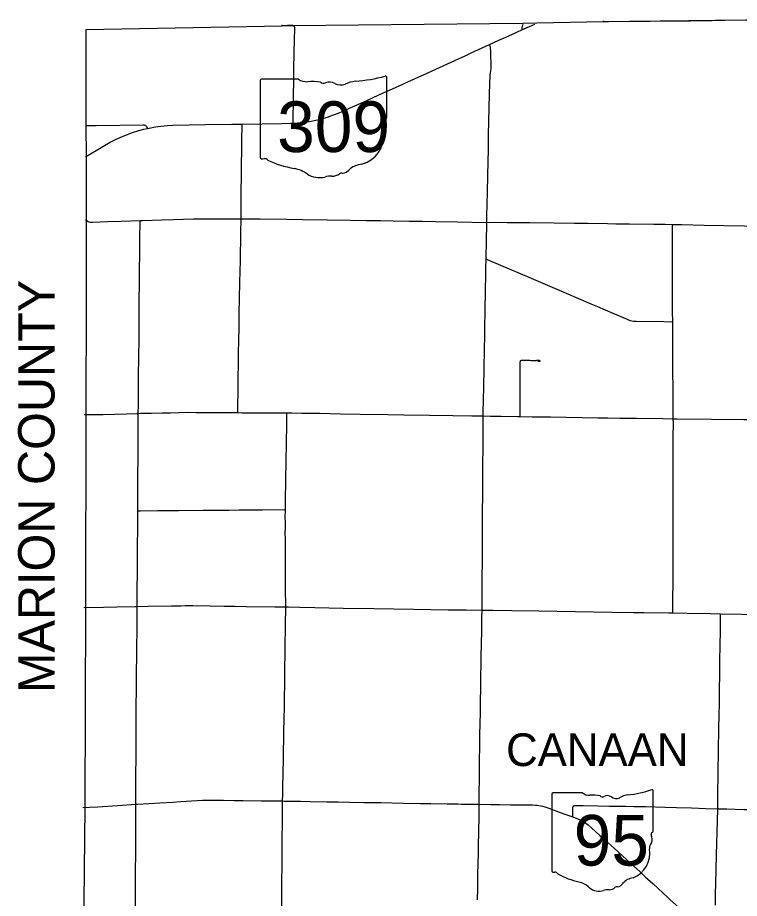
# Model space of a CAD drawing. Extents: x 1815539 to 1947826, y 273303 to 993194.
# Drawn here: x 1839504 to 1859353, y 939932 to 964155 of the extents above; entities that cross this region are included whole.
import ezdxf

# ---------------------------------------------------------------- set-up
doc = ezdxf.new("R2010")
doc.units = 0
for name, color, linetype in [('GM_X_Adjacent_County_Text', 7, 'Continuous'), ('GM_X_County', 7, 'Continuous'), ('GM_X_County_Road', 7, 'Continuous'), ('GM_X_State_Route', 7, 'Continuous'), ('GM_X_Township', 7, 'Continuous'), ('GM_X_Township_Road', 7, 'Continuous'), ('GM_X_Township_Text', 7, 'Continuous'), ('SC_Shading3', 7, 'Continuous')]:
    doc.layers.add(name, color=color, linetype=linetype)

msp = doc.modelspace()

# ---------------------------------------------------------------- linework, layer by layer
at = {"layer": 'GM_X_County'}
msp.add_lwpolyline([(1841249, 932050), (1841362, 942439), (1841377, 947941), (1841392, 953202), (1841402, 956488), (1841397, 958575), (1841394, 960342), (1841392, 961182), (1841387, 963824), (1846780, 963929), (1847071, 963938), (1852487, 963992), (1853408, 964004), (1853786, 964009), (1855618, 964050), (1860298, 964101)], dxfattribs=at)
at = {"layer": 'GM_X_County_Road'}
for points in [[(1853373, 963817), (1853375, 963837), (1853377, 963853), (1853378, 963867), (1853381, 963885), (1853390, 963915), (1853400, 963949), (1853409, 963974)], [(1852406, 958524), (1852407, 958550), (1852407, 958648), (1852417, 959074), (1852422, 959304), (1852425, 959468), (1852431, 959714), (1852436, 959911), (1852440, 960091), (1852452, 960632), (1852455, 960845), (1852458, 961026), (1852463, 961206), (1852466, 961354), (1852473, 961616), (1852475, 961764), (1852479, 961961), (1852483, 962091), (1852488, 962288), (1852491, 962403), (1852495, 962485), (1852502, 962567), (1852512, 962648), (1852518, 962689), (1852523, 962750), (1852529, 962826), (1852531, 962880), (1852527, 962951), (1852521, 963061), (1852517, 963173), (1852515, 963242), (1852512, 963301), (1852508, 963340), (1852501, 963364), (1852495, 963379), (1852482, 963411)], [(1841368, 958601), (1841416, 958567), (1841440, 958551), (1841466, 958540), (1841500, 958533), (1841565, 958530), (1841975, 958543), (1842352, 958555), (1842871, 958572)], [(1842871, 958572), (1842943, 958574), (1843467, 958592), (1843795, 958605), (1844337, 958622), (1844616, 958625), (1845108, 958622), (1845404, 958622), (1845650, 958621)], [(1845650, 958621), (1846175, 958620), (1846897, 958613), (1847340, 958606), (1848028, 958595), (1848652, 958584), (1849094, 958577), (1849291, 958576), (1849488, 958573), (1849833, 958567), (1850276, 958561), (1850637, 958556), (1850998, 958549), (1851605, 958541), (1852376, 958524), (1852406, 958524)], [(1852388, 957514), (1852390, 957647), (1852396, 957910), (1852398, 958107), (1852404, 958388), (1852406, 958524)], [(1852406, 958524), (1852606, 958527), (1852967, 958522), (1853590, 958516), (1854263, 958508), (1854821, 958502), (1855182, 958498), (1855723, 958490), (1855953, 958487), (1856330, 958485), (1857003, 958476), (1857315, 958470), (1857510, 958468)], [(1857510, 958468), (1857774, 958464), (1858381, 958450), (1859497, 958428), (1860219, 958415), (1860263, 958416)], [(1857520, 955791), (1857518, 956073), (1857517, 956828), (1857517, 957452), (1857511, 958240), (1857510, 958436), (1857510, 958468)], [(1852307, 953199), (1852310, 953285), (1852317, 953662), (1852322, 953974), (1852333, 954531), (1852341, 955007), (1852350, 955433), (1852354, 955647), (1852355, 955761), (1852358, 955942), (1852363, 956122), (1852366, 956270), (1852370, 956466), (1852374, 956712), (1852378, 957008), (1852383, 957270), (1852388, 957514)], [(1852388, 957514), (1852417, 957502), (1852781, 957351), (1853566, 957016), (1854593, 956576), (1855272, 956286), (1855453, 956209), (1855876, 956028), (1856268, 955857), (1856344, 955828), (1856392, 955815), (1856441, 955807), (1856523, 955802), (1857278, 955795), (1857492, 955792), (1857520, 955791)], [(1857535, 953123), (1857535, 953163), (1857533, 953474), (1857533, 953573), (1857530, 953835), (1857530, 954032), (1857526, 954341), (1857525, 954521), (1857523, 954621), (1857523, 954630), (1857523, 954662), (1857522, 954793), (1857521, 954941), (1857520, 954974), (1857520, 955072), (1857519, 955236), (1857520, 955483), (1857521, 955712), (1857520, 955791)], [(1842823, 953269), (1842895, 953273), (1843187, 953278), (1843482, 953283), (1843712, 953289), (1844171, 953301), (1844417, 953299), (1844728, 953299), (1845056, 953294), (1845303, 953294), (1845434, 953293), (1845563, 953291)], [(1845563, 953291), (1845680, 953290), (1845991, 953290), (1846336, 953289), (1846598, 953289), (1846910, 953285)], [(1846910, 953285), (1847041, 953284), (1847320, 953280), (1847812, 953272), (1848386, 953262), (1848928, 953253), (1849682, 953242), (1850125, 953233), (1850831, 953221), (1851470, 953213), (1851995, 953202), (1852307, 953199)], [(1852275, 947862), (1852275, 947904), (1852277, 948166), (1852279, 948445), (1852280, 948593), (1852282, 948839), (1852284, 949118), (1852285, 949364), (1852287, 949643), (1852289, 949856), (1852289, 950118), (1852292, 950479), (1852293, 950611), (1852294, 950988), (1852295, 951300), (1852296, 951464), (1852299, 951677), (1852302, 951956), (1852304, 952235), (1852303, 952514), (1852308, 953055), (1852307, 953199)], [(1852307, 953199), (1852504, 953195), (1852799, 953190), (1853258, 953183), (1853321, 953182)], [(1853321, 953182), (1853652, 953178), (1854160, 953171), (1855456, 953151), (1855735, 953148), (1856063, 953143), (1856523, 953136), (1857244, 953126), (1857535, 953123)], [(1857525, 947784), (1857525, 947829), (1857525, 947976), (1857528, 948814), (1857529, 949322), (1857531, 950127), (1857531, 950471), (1857530, 950717), (1857529, 950881), (1857533, 951259), (1857535, 951686), (1857534, 951899), (1857535, 952096), (1857535, 952621), (1857537, 952998), (1857535, 953123)], [(1857535, 953123), (1857638, 953122), (1858590, 953112), (1859475, 953106), (1860033, 953098), (1860279, 953094), (1860722, 953087), (1861083, 953078), (1861561, 953071)], [(1852194, 942521), (1852194, 942655), (1852196, 942769), (1852198, 942933), (1852202, 943114), (1852204, 943196), (1852206, 943425), (1852210, 943770), (1852214, 944065), (1852219, 944361), (1852226, 944803), (1852229, 944984), (1852231, 945230), (1852236, 945444), (1852239, 945625), (1852242, 945886), (1852246, 946148), (1852248, 946280), (1852255, 946575), (1852268, 947288), (1852273, 947658), (1852275, 947862)], [(1852275, 947862), (1852571, 947859), (1853096, 947849), (1853834, 947836), (1854835, 947819), (1855851, 947801), (1856442, 947795), (1856721, 947794), (1857410, 947786), (1857525, 947784)], [(1857525, 947784), (1857918, 947778), (1858558, 947768), (1858837, 947762)], [(1858837, 947762), (1860001, 947739), (1860542, 947729), (1861455, 947708)], [(1846744, 937289), (1846745, 937386), (1846749, 937632), (1846751, 937879), (1846755, 938518), (1846759, 938879), (1846764, 939371), (1846766, 939650), (1846769, 939830), (1846771, 939945), (1846771, 940142), (1846772, 940470), (1846776, 940765), (1846777, 940978), (1846779, 941142), (1846780, 941405), (1846782, 941634), (1846785, 941946), (1846787, 942126), (1846788, 942340), (1846790, 942611)], [(1852151, 939889), (1852157, 940217), (1852158, 940315), (1852159, 940396), (1852163, 940577), (1852171, 940905), (1852175, 941151), (1852182, 941463), (1852186, 941693), (1852191, 941907), (1852192, 941959), (1852193, 942002), (1852194, 942033), (1852195, 942082), (1852195, 942147), (1852196, 942196), (1852197, 942262), (1852196, 942327), (1852196, 942394), (1852194, 942507), (1852194, 942521)], [(1854769, 942173), (1854769, 942179), (1854772, 942222), (1854773, 942245), (1854774, 942278), (1854773, 942377), (1854773, 942426), (1854774, 942442), (1854778, 942457), (1854785, 942470), (1854796, 942479), (1854810, 942486), (1854825, 942489), (1854841, 942490), (1854857, 942490), (1854922, 942488), (1855053, 942485), (1855463, 942479), (1855775, 942472), (1856070, 942467), (1856218, 942464), (1856464, 942461), (1856775, 942455), (1857316, 942444), (1857628, 942434), (1858037, 942419), (1858431, 942405), (1858756, 942397)], [(1858756, 942397), (1858775, 942396), (1859005, 942391), (1859480, 942381), (1859759, 942376), (1859972, 942371), (1860267, 942366), (1860562, 942361), (1860789, 942359)]]:
    msp.add_lwpolyline(points, dxfattribs=at)
at = {"layer": 'GM_X_State_Route'}
for points in [[(1851809, 963104), (1851980, 963182), (1852482, 963411), (1852741, 963530), (1852995, 963644), (1853249, 963761), (1853373, 963817), (1853728, 963978)], [(1848710, 961697), (1848842, 961756), (1849111, 961878), (1849440, 962027), (1849664, 962130), (1849978, 962271), (1850352, 962441), (1850665, 962584), (1851009, 962740), (1851532, 962978), (1851809, 963104)], [(1841375, 960325), (1841849, 960610), (1842048, 960725), (1842179, 960792), (1842357, 960876), (1842524, 960944), (1842663, 960994), (1842835, 961047), (1842977, 961086), (1843075, 961107), (1843121, 961118), (1843299, 961150), (1843445, 961171), (1843624, 961188), (1843772, 961195), (1844674, 961212), (1845396, 961223), (1845676, 961227), (1846774, 961244), (1847004, 961250), (1847082, 961254), (1847201, 961260), (1847348, 961276), (1847527, 961302), (1847705, 961336), (1847864, 961374), (1848022, 961420), (1848194, 961477), (1848347, 961536), (1848513, 961608), (1848710, 961697)], [(1841298, 942429), (1841481, 942439), (1841710, 942452), (1842250, 942486), (1842755, 942519), (1842807, 942522), (1843413, 942561), (1843773, 942582), (1843986, 942595), (1844444, 942622), (1844592, 942630), (1844723, 942634), (1844904, 942635), (1845166, 942632), (1845462, 942626), (1845708, 942624), (1846200, 942617), (1846790, 942611), (1846840, 942610), (1847283, 942604), (1847545, 942598), (1848005, 942591), (1848316, 942585), (1848628, 942580), (1849022, 942572), (1849497, 942565), (1850104, 942555), (1850580, 942545), (1850842, 942542), (1850864, 942542)], [(1850864, 942542), (1851318, 942533), (1851613, 942529), (1851713, 942527)], [(1851713, 942527), (1851892, 942524), (1852188, 942521), (1852194, 942521), (1852515, 942517), (1852549, 942517), (1852580, 942516), (1852645, 942514), (1852759, 942513), (1853054, 942508), (1853300, 942505), (1853661, 942501), (1853744, 942499), (1853793, 942495), (1853842, 942488), (1853891, 942479), (1853938, 942466), (1854001, 942447), (1854110, 942409), (1854527, 942259), (1854769, 942173), (1854882, 942132), (1854959, 942103), (1855004, 942083), (1855048, 942059), (1855090, 942032), (1855129, 942003), (1855193, 941951), (1855292, 941864), (1855511, 941666), (1855658, 941535), (1855829, 941382), (1856012, 941217), (1856145, 941096), (1856352, 940908), (1856533, 940742), (1856612, 940668)], [(1856612, 940668), (1856761, 940529), (1856978, 940328), (1857255, 940073), (1857376, 939962), (1857441, 939903), (1857617, 939744), (1857765, 939609), (1858081, 939323), (1858374, 939060), (1858608, 938848)]]:
    msp.add_lwpolyline(points, dxfattribs=at)
at = {"layer": 'GM_X_Township'}
msp.add_lwpolyline([(1841387, 963824), (1846780, 963929), (1847071, 963938), (1852487, 963992), (1853408, 964004), (1853786, 964009), (1855618, 964050), (1860298, 964101), (1862894, 964131), (1865546, 964151), (1868643, 964155), (1868586, 961770), (1868495, 957891), (1868480, 956467), (1868459, 955370), (1868335, 951151), (1868323, 950291), (1862794, 950174), (1862758, 947658), (1862681, 942300), (1862643, 939637)], dxfattribs=at)
at = {"layer": 'GM_X_Township_Road'}
for points in [[(1855601, 964061), (1855612, 964055), (1855624, 964052), (1855640, 964050), (1855755, 964047), (1856329, 964055), (1856608, 964056), (1856903, 964058), (1857526, 964065), (1858001, 964070), (1858591, 964078), (1858689, 964080), (1858755, 964080), (1858951, 964083), (1859771, 964094), (1860296, 964103)], [(1846984, 963939), (1846923, 963935), (1846841, 963930), (1846809, 963931), (1846792, 963933), (1846779, 963935), (1846772, 963938), (1846765, 963942)], [(1847120, 963897), (1847117, 963903), (1847113, 963910), (1847107, 963917), (1847100, 963924), (1847087, 963932), (1847071, 963938), (1847054, 963940), (1847022, 963941), (1846984, 963939)], [(1847082, 961254), (1847083, 961298), (1847086, 961527), (1847087, 961708), (1847092, 962003), (1847098, 962413), (1847104, 962757), (1847111, 963167), (1847119, 963578), (1847131, 963823), (1847129, 963860), (1847128, 963870), (1847126, 963881), (1847123, 963889), (1847120, 963897)], [(1841379, 961184), (1841667, 961183), (1842953, 961207), (1842986, 961205), (1843003, 961201), (1843018, 961193), (1843032, 961182), (1843043, 961168), (1843051, 961153), (1843075, 961107)], [(1845650, 958621), (1845651, 958739), (1845651, 958821), (1845651, 958907), (1845651, 959115), (1845652, 959246), (1845656, 959412), (1845656, 959539), (1845658, 959634), (1845660, 959718), (1845662, 959852), (1845662, 959951), (1845663, 960148), (1845664, 960263), (1845666, 960361), (1845667, 960459), (1845669, 960673), (1845673, 960886), (1845675, 961099), (1845675, 961190), (1845676, 961227)], [(1842823, 953269), (1842825, 953508), (1842828, 954082), (1842830, 954345), (1842832, 954476), (1842837, 954640), (1842839, 954935), (1842843, 955214), (1842846, 955477), (1842848, 955674), (1842849, 956002), (1842851, 956231), (1842851, 956510), (1842855, 956707), (1842858, 957002), (1842858, 957134), (1842860, 957298), (1842864, 957577), (1842866, 957757), (1842867, 957970), (1842868, 958134), (1842871, 958495), (1842871, 958544), (1842871, 958572)], [(1845632, 957512), (1845636, 957690), (1845642, 958018), (1845644, 958247), (1845650, 958608), (1845650, 958621)], [(1845562, 953524), (1845566, 953837), (1845570, 954083), (1845573, 954280), (1845578, 954607), (1845582, 954935), (1845590, 955263), (1845595, 955640), (1845601, 955968), (1845609, 956477), (1845617, 956821), (1845624, 957231), (1845629, 957411), (1845632, 957512)], [(1853321, 953182), (1853321, 953211), (1853322, 953539), (1853326, 954179), (1853328, 954425), (1853328, 954655), (1853329, 954676)], [(1853329, 954676), (1853330, 954704), (1853334, 954719), (1853347, 954729), (1853363, 954733), (1853428, 954733), (1853457, 954734), (1853501, 954734), (1853590, 954731), (1853630, 954729), (1853648, 954728), (1853727, 954728), (1853773, 954729), (1853787, 954730), (1853802, 954732), (1853818, 954735), (1853823, 954735), (1853829, 954735), (1853834, 954735), (1853839, 954734), (1853844, 954733), (1853849, 954731), (1853853, 954729), (1853857, 954727), (1853859, 954724), (1853861, 954721), (1853863, 954718), (1853863, 954713), (1853864, 954709), (1853863, 954705), (1853863, 954702), (1853861, 954698), (1853857, 954694), (1853854, 954693), (1853849, 954693), (1853843, 954693), (1853839, 954694), (1853835, 954695), (1853828, 954698), (1853825, 954700), (1853821, 954702), (1853816, 954708), (1853813, 954712)], [(1845563, 953291), (1845562, 953312), (1845561, 953329), (1845561, 953427), (1845562, 953524)], [(1841344, 953239), (1841510, 953238), (1841856, 953244), (1842500, 953261), (1842780, 953268), (1842823, 953269)], [(1842808, 950593), (1842809, 950801), (1842811, 951129), (1842813, 951375), (1842814, 951589), (1842816, 952015), (1842818, 952261), (1842820, 952573), (1842823, 952950), (1842823, 953213), (1842823, 953269)], [(1846871, 950623), (1846872, 950769), (1846874, 950982), (1846879, 951311), (1846882, 951524), (1846888, 951885), (1846896, 952509), (1846903, 952903), (1846909, 953248), (1846910, 953285)], [(1842791, 947962), (1842791, 948078), (1842791, 948209), (1842792, 948357), (1842795, 948537), (1842798, 948800), (1842800, 949013), (1842803, 949308), (1842804, 949522), (1842805, 949718), (1842807, 950014), (1842808, 950325), (1842808, 950506), (1842808, 950593)], [(1842808, 950593), (1842829, 950593), (1842886, 950594), (1843362, 950599), (1843937, 950603), (1844611, 950608), (1844905, 950613), (1845167, 950612), (1845314, 950613), (1845593, 950617), (1845840, 950615), (1846234, 950617), (1846842, 950623), (1846871, 950623)], [(1846876, 947949), (1846876, 948028), (1846874, 948389), (1846870, 948767), (1846869, 949539), (1846869, 949801), (1846866, 949998), (1846868, 950113), (1846868, 950211), (1846867, 950277), (1846866, 950408), (1846871, 950605), (1846871, 950623)], [(1841322, 947936), (1841867, 947941), (1842228, 947949), (1842736, 947960), (1842791, 947962)], [(1842764, 945077), (1842764, 945109), (1842767, 945306), (1842768, 945388), (1842769, 945519), (1842771, 945699), (1842774, 945962), (1842776, 946191), (1842778, 946552), (1842781, 946683), (1842784, 946848), (1842788, 947307), (1842789, 947602), (1842790, 947766), (1842791, 947930), (1842791, 947962)], [(1842791, 947962), (1843097, 947970), (1843737, 947977), (1843994, 947981)], [(1843994, 947981), (1844113, 947983), (1844327, 947983), (1844802, 947978), (1845180, 947971), (1845475, 947968), (1845787, 947963), (1846574, 947954), (1846876, 947949)], [(1846790, 942611), (1846790, 942645), (1846793, 942760), (1846798, 943006), (1846806, 943350), (1846813, 943794), (1846817, 944023), (1846821, 944286), (1846825, 944499), (1846834, 944893), (1846839, 945172), (1846843, 945435), (1846849, 945845), (1846850, 945927), (1846851, 946009), (1846855, 946371), (1846858, 946551), (1846861, 946748), (1846865, 946978), (1846869, 947290), (1846874, 947618), (1846876, 947766), (1846876, 947949)], [(1846876, 947949), (1846951, 947948), (1847263, 947943), (1847673, 947934), (1848461, 947917), (1849297, 947901), (1850396, 947885), (1851348, 947872), (1851840, 947864), (1852260, 947862), (1852275, 947862)], [(1858756, 942397), (1858763, 942760), (1858781, 944006), (1858791, 944596), (1858797, 944989), (1858802, 945284), (1858807, 945694), (1858814, 946071), (1858820, 946513), (1858824, 946841), (1858833, 947349), (1858837, 947709), (1858837, 947762)], [(1842755, 942519), (1842755, 942550), (1842756, 942730), (1842757, 943026), (1842759, 943255), (1842763, 943879), (1842763, 944404), (1842762, 944568), (1842763, 944781), (1842764, 945077)], [(1842730, 937328), (1842731, 937497), (1842732, 937907), (1842735, 938153), (1842739, 938596), (1842740, 938875), (1842741, 939072), (1842743, 939252), (1842745, 939597), (1842748, 940007), (1842748, 940269), (1842750, 940762), (1842751, 941073), (1842752, 941303), (1842754, 941828), (1842755, 942287), (1842755, 942452), (1842755, 942519)], [(1858694, 939749), (1858700, 940073), (1858705, 940319), (1858726, 941138), (1858749, 942055), (1858756, 942397)]]:
    msp.add_lwpolyline(points, dxfattribs=at)
at = {"layer": 'SC_Shading3'}
for p, q in [((1846177, 962423), (1846177, 960309)), ((1847230, 962459), (1846211, 962459)), ((1849657, 961406), (1849657, 962511)), ((1849657, 961406), (1849657, 961406)), ((1854195, 942799), (1854195, 940685)), ((1855038, 942835), (1854222, 942835)), ((1856979, 941782), (1856979, 942887)), ((1856979, 941782), (1856979, 941782))]:
    msp.add_line(p, q, dxfattribs=at)
for centre, radius, start, end in [((1854227, 942803), 32.3, 98.1301, 188.1301), ((1855232, 943080), 313, 231.6195, 271.1119), ((1855336, 941649), 1123, 80.4867, 94.9883), ((1855591, 942814), 90.3, 219.7921, 297.1024), ((1855723, 942570), 188, 54.4667, 119.1411), ((1856364, 942190), 594, 97.3462, 120.7689), ((1855988, 945716), 2953, 275.8445, 288.9065), ((1856949, 942892), 31, 351.8621, 97.738), ((1855966, 942905), 226, 233.8562, 294.8282), ((1856946, 941778), 33.2, 289.6038, 7.7341), ((1856972, 941701), 48, 107.944, 210.337), ((1856667, 941561), 288, 340.033, 23.6496), ((1856153, 941179), 739, 292.3089, 8.9858), ((1857090, 941319), 210, 136.8065, 186.9296), ((1854227, 940681), 32.5, 171.9584, 258.3066), ((1854232, 940897), 248, 267.339, 280.6039), ((1854283, 940564), 89.5, 29.7484, 93.2717), ((1855414, 942462), 2132, 240.4129, 257.1985), ((1854778, 939736), 667, 47.1842, 75.836), ((1855952, 940481), 239, 282.8732, 323.2771), ((1856464, 940092), 404, 94.4031, 142.5768), ((1855499, 940553), 423, 230.7004, 286.2918), ((1855744, 939822), 348, 85.6951, 111.2099), ((1855775, 940395), 226, 268.777, 315.5493), ((1855979, 940190), 63.5, 65.7517, 132.6484)]:
    msp.add_arc(centre, radius, start, end, dxfattribs=at)
for centre, major_axis, start_param, end_param in [((1846217, 962427), (40.3, 0), 1.712693, 3.28349), ((1847473, 962704), (391, 0), 4.042523, 4.731795), ((1847603, 961273), (1404, 0), 1.404758, 1.657858), ((1847921, 962438), (113, 0), 3.836095, 5.185415), ((1848087, 962194), (235, 0), 0.950623, 2.079405), ((1848888, 961814), (743, 0), 1.699011, 2.107814), ((1848417, 965340), (3691, 0), 4.814394, 5.042369), ((1849619, 962516), (38.7, 0), 6.141152, 7.989035), ((1848390, 962529), (282, 0), 4.081561, 5.145723), ((1849616, 961402), (41.5, 0), 5.05454, 6.418171), ((1849648, 961325), (60, 0), 1.883978, 3.671073), ((1849267, 961185), (360, 0), 5.934695, 6.695948), ((1848624, 960803), (923, 0), 5.101752, 6.440018), ((1849796, 960943), (262, 0), 2.387724, 3.262537), ((1846217, 960305), (40.7, 0), 3.00124, 4.508301), ((1846223, 960521), (310, 0), 4.665946, 4.897461), ((1846287, 960188), (112, 0), 0.519207, 1.627899), ((1847700, 962086), (2665, 0), 4.195997, 4.488961), ((1846905, 959360), (834, 0), 0.823519, 1.323587), ((1848373, 960105), (298, 0), 4.937069, 5.64225), ((1849013, 959716), (506, 0), 1.647645, 2.488434), ((1847807, 960177), (529, 0), 4.026481, 4.996735), ((1848113, 959446), (435, 0), 1.495662, 1.94098), ((1848152, 960019), (282, 0), 4.691044, 5.507374), ((1848407, 959814), (79.4, 0), 1.147584, 2.315152)]:
    msp.add_ellipse(centre, major_axis=major_axis, ratio=0.8, start_param=start_param, end_param=end_param, dxfattribs=at)

# ---------------------------------------------------------------- texts
at = {"layer": 'GM_X_Adjacent_County_Text'}
msp.add_text('MARION COUNTY', height=1000, rotation=90, dxfattribs=at).set_placement((1840519, 945579))
at = {"layer": 'GM_X_Township_Text'}
msp.add_text('CANAAN', height=900, rotation=0, dxfattribs=at).set_placement((1852937, 943571))
at = {"layer": 'SC_Shading3'}
for s, p in [('309', (1846641, 960458)), ('95', (1854796, 940834))]:
    msp.add_text(s, height=1392.2, dxfattribs=at).set_placement(p)

doc.saveas('drawing.dxf')
